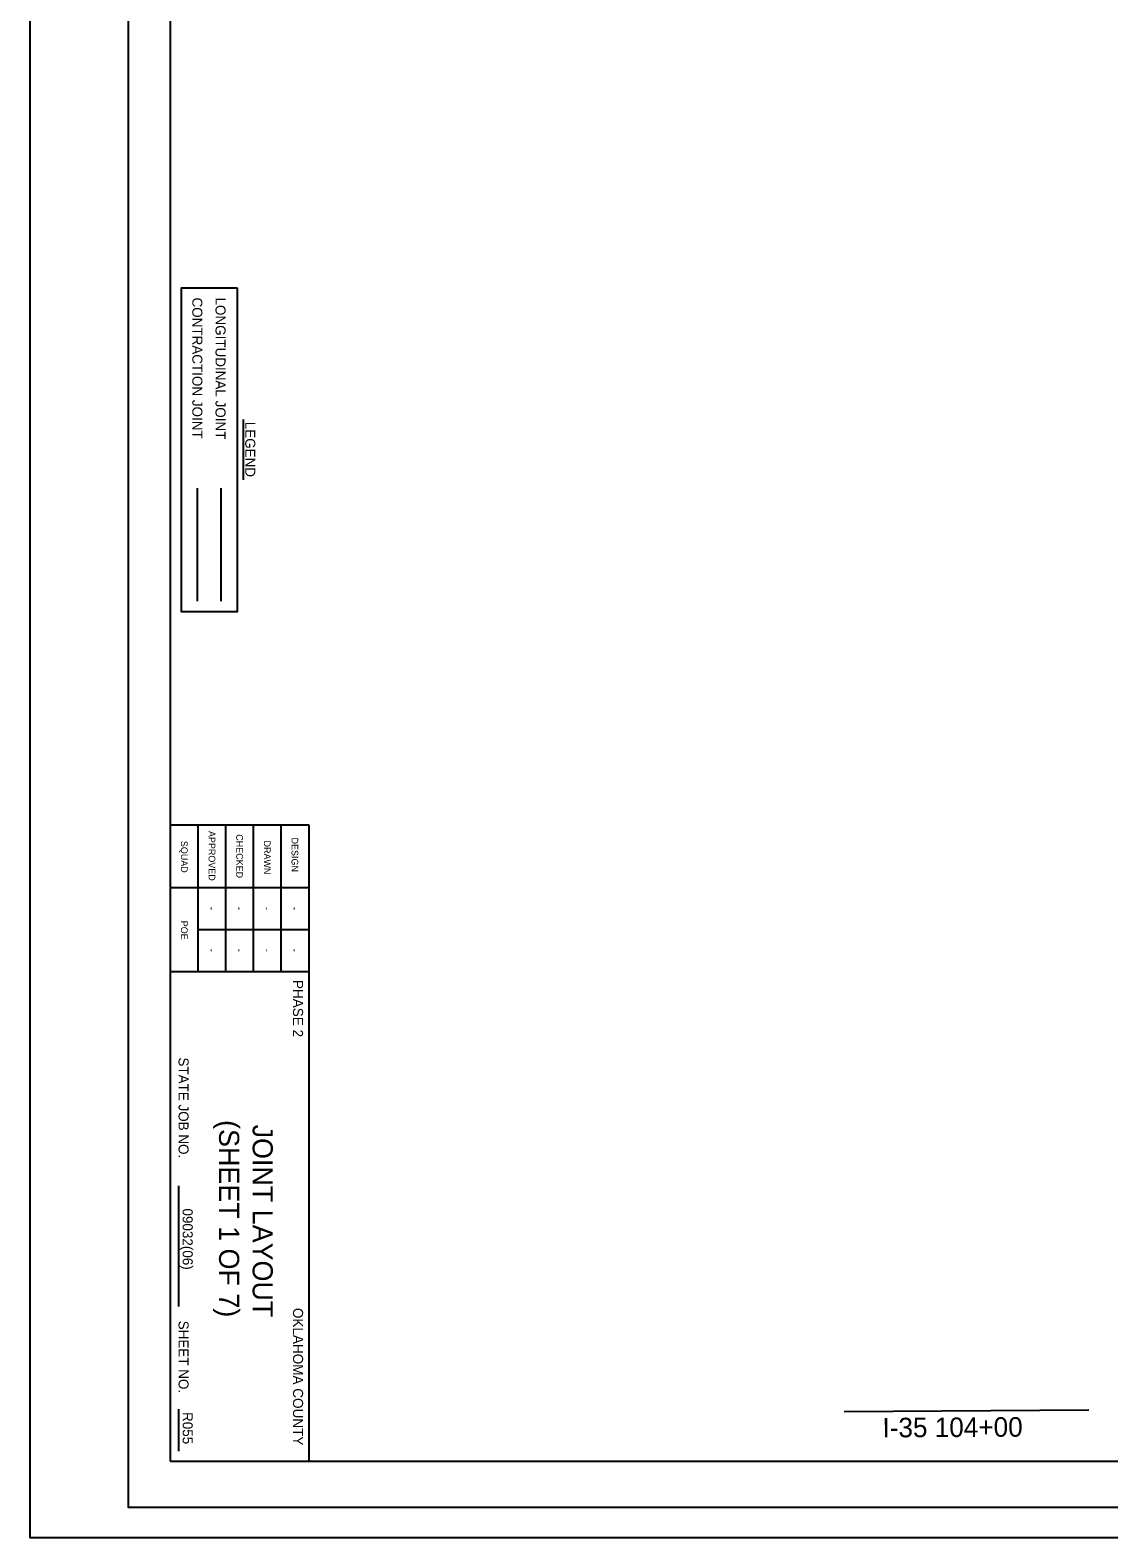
# Model space of a CAD drawing. Extents: x 2150474 to 2151194, y 145574 to 146654.
# Drawn here: x 2150474 to 2150860, y 145574 to 146114 of the extents above; entities that cross this region are included whole.
import ezdxf

# ---------------------------------------------------------------- set-up
doc = ezdxf.new("R2010")
doc.units = 0
for name, color, linetype in [('PR_Joint_Contraction', 7, 'Continuous'), ('PR_Joint_Long', 7, 'Continuous'), ('PR_Txt', 7, 'Continuous'), ('SHT_Match_Lines', 7, 'Continuous'), ('SHT_Plot_Shape_Full', 7, 'Continuous'), ('SHT_Plot_Shape_Half', 7, 'Continuous'), ('SHT_Sheet_Border', 7, 'Continuous'), ('SHT_Standard_Sheet_Lines', 7, 'Continuous'), ('SHT_Standard_Sheet_Txt', 7, 'Continuous')]:
    doc.layers.add(name, color=color, linetype=linetype)

msp = doc.modelspace()

# ---------------------------------------------------------------- linework, layer by layer
at = {"layer": 'PR_Joint_Contraction'}
msp.add_lwpolyline([(2150533.5, 145949.67), (2150533.5, 145909.24)], dxfattribs=at)
at = {"layer": 'PR_Joint_Long'}
msp.add_line((2150541.92, 145949.67), (2150541.92, 145909.24), dxfattribs=at)
at = {"layer": 'PR_Txt'}
msp.add_line((2150549.86, 145974.27), (2150549.86, 145952.66), dxfattribs=at)
msp.add_lwpolyline([(2150547.79, 146021.48), (2150547.79, 145905.46), (2150527.84, 145905.46), (2150527.84, 146021.48)], close=True, dxfattribs=at)
at = {"layer": 'SHT_Match_Lines'}
msp.add_line((2150852.72, 145619.43), (2150765.12, 145618.9), dxfattribs=at)
at = {"layer": 'SHT_Plot_Shape_Full'}
msp.add_lwpolyline([(2151193.63, 146653.76), (2151193.63, 145573.76), (2150473.63, 145573.76), (2150473.63, 146653.76)], close=True, dxfattribs=at)
at = {"layer": 'SHT_Plot_Shape_Half'}
msp.add_lwpolyline([(2151168.88, 146604.63), (2151168.88, 145584.63), (2150508.88, 145584.63), (2150508.88, 146604.63)], close=True, dxfattribs=at)
at = {"layer": 'SHT_Sheet_Border'}
for p, q in [((2150523.88, 145829.13), (2150573.38, 145829.13)), ((2150573.38, 145829.13), (2150573.39, 145601.13)), ((2150523.88, 145776.63), (2150573.41, 145776.63))]:
    msp.add_line(p, q, dxfattribs=at)
msp.add_lwpolyline([(2150523.88, 145601.13), (2150523.88, 146546.13), (2151153.88, 146546.13), (2151153.88, 145601.13)], close=True, dxfattribs=at)
at = {"layer": 'SHT_Standard_Sheet_Lines'}
for p, q in [((2150523.88, 145806.63), (2150573.41, 145806.63)), ((2150533.79, 145791.63), (2150573.41, 145791.63)), ((2150526.77, 145699.81), (2150526.77, 145656.6)), ((2150526.77, 145619.87), (2150526.77, 145604.79))]:
    msp.add_line(p, q, dxfattribs=at)
for points in [[(2150533.78, 145776.63), (2150533.78, 145829.13)], [(2150543.68, 145776.63), (2150543.68, 145829.13)], [(2150553.58, 145776.63), (2150553.58, 145829.13)], [(2150563.48, 145776.63), (2150563.48, 145829.13)]]:
    msp.add_lwpolyline(points, dxfattribs=at)

# ---------------------------------------------------------------- texts
at = {"layer": 'PR_Txt'}
for s, height, rotation, p in [('CONTRACTION JOINT', 3.6, 270, (2150531.7, 146017.99)), ('LONGITUDINAL JOINT', 3.6, 270, (2150540.01, 146017.99)), ('LEGEND', 3.6, 270, (2150550.65, 145973.49)), ('I-35 104+00', 7, 0.3078, (2150778.86, 145609.73))]:
    msp.add_text(s, height=height, rotation=rotation, dxfattribs=at).set_placement(p)
at = {"layer": 'SHT_Standard_Sheet_Txt'}
for s, height, p in [('SQUAD', 2.4, (2150527.63, 145823.39)), ('APPROVED', 2.4, (2150537.53, 145826.93)), ('CHECKED', 2.4, (2150547.43, 145825.75)), ('DRAWN', 2.4, (2150557.33, 145823.49)), ('DESIGN', 2.4, (2150567.23, 145824.57)), ('-', 2.4, (2150537.52, 145799.72)), ('-', 2.4, (2150547.42, 145799.72)), ('-', 2.4, (2150557.32, 145799.72)), ('-', 2.4, (2150567.25, 145799.72)), ('POE', 2.4, (2150527.63, 145794.78)), ('-', 2.4, (2150537.52, 145784.72)), ('-', 2.4, (2150547.42, 145784.72)), ('-', 2.4, (2150557.32, 145784.72)), ('-', 2.4, (2150567.25, 145784.72)), ('PHASE 2', 3.621, (2150567.75, 145773.57)), ('STATE JOB NO.', 3.6, (2150526.77, 145745.82)), ('(SHEET 1 OF 7)', 7.2, (2150541.29, 145723.38)), ('JOINT LAYOUT', 7.2, (2150553.31, 145721.76)), ('09032(06)', 3.6, (2150528.25, 145691.73)), ('OKLAHOMA COUNTY', 3.6211, (2150567.75, 145656.11)), ('SHEET NO. ', 3.6, (2150526.77, 145651.52)), ('R055', 3.6, (2150528.25, 145618.8))]:
    msp.add_text(s, height=height, rotation=270, dxfattribs=at).set_placement(p)

doc.saveas('drawing.dxf')
